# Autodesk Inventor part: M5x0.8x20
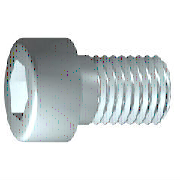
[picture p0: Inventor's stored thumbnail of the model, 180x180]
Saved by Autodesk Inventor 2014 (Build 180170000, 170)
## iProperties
IsCustomPart: 0
Created: 2015-11
Part Number: M5x0.8x20
Material: 스테인리스강
Description: 6각머리 태핑 나사
Document SubType Name: Modeling
Standard: KS B 1003
Designer: mdu
Standards Organization: KS
Language: ko-KR
Size Designation: M 5 x 20
Categories: <MemberInstance><Categories><Category DisplayName="조임쇠" InternalName="e4da775c-781d-43d5-af7c-5136215cf5a6" Mnemonic="FSTN"><Category DisplayName="볼트" InternalN
Density: 8.08 g/cm^3
Appearance: 반광택
Mass: 5.10181 g
Surface Area: 5.88237 cm^2
Volume: 0.631412 cm^3
Author: mdu
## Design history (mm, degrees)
sketch "스케치1"
  geometry: L1 (-1.167, 0)-(20, 0); L2 (20, 0)-(20, 2.5); L3 (20, 2.5)-(2, 2.5); L4 (2, 2.5)-(1.509, 2.5); L5 (1.509, 2.5)-(0, 2.5); L6 (0, 2.5)-(0, 4.25); L7 (0, 4.25)-(-5, 4.25); L8 (-5, 4.25)-(-5, 2.309); L9 (-5, 2.309)-(-2.5, 2.309); L10 (-2.5, 2.309)-(-1.167, 0); L11 (-10, 0)-(25, 0) reference; L12 (0, -0.85)-(0, 5.1) reference; L13 (2, 2.5)-(0, 2.5)
  constraints: 22 end point, 6 parallel, 2 collinear, 2 perpendicular, 1 horizontal, 1 point on line
  dimensions: "d1" = 18 distance from line of L3.end L2 (= GEL); "d2" = 0.49086 distance of L4.end L3.end (computed from GAL); "d3" = 5 distance between parallel lines of L8 L6 (= KOH); "d4" = 2.5 distance of L8.end L9.end (= INTI); "d5" = 60 deg angle of L10 L1; "d6" = 5 diameter of L3 L1 (= GD); "d7" = 5 diameter of L5 L1 (= BDM); "d8" = 4.6188 diameter of L9 L1 (= 1.1547 x SW); "d9" = 8.5 diameter of L7 L1 (= KOD); "d26" = 20 distance between parallel lines of L12 L2 (= NLG)
revolve "본체" sketch "스케치1" stored, may be unused: angle "d10" = 90 deg
sketch "스케치2"
  geometry: L1 (0, -5.95)-(0, 5.95) reference; L2 (-5.95, 0)-(5.95, 0) reference; L3 (2.309, 0)-(1.155, -2); L4 (1.155, -2)-(-1.155, -2); L5 (-1.155, -2)-(-2.309, 0); L6 (-2.309, 0)-(-1.155, 2); L7 (-1.155, 2)-(1.155, 2); L8 (1.155, 2)-(2.309, 0); 2 further points
  constraints: 12 end point, 1 coincident, 1 horizontal alignment, 1 point on line, 12 other
extrude "슬롯" join sketch "스케치2" stored distance "d11" = 10; taper "d12" = 0 deg
workplane "Work Plane1"
fillet "Fillet2" dims "d30" = 0.1 (= R)
body "Solid1"
fillet "모깎기1" dims "d17" = 0.5 (= RR)
feature "스레드" dims "d13" = 18 (= GEL), "d14" = 0
chamfer "모따기1" distance "d15" = 0.49076 (= -0.5 x SPD + 0.5 x GD); stored, may be unused: second distance "d16" = 0.49076 (= GUL), angle "d27" = 45 deg
other parameters: "GD" = 5 (= NND) [user parameter; used in 2 equation terms], "NLG" = 20 [user parameter; used in 1 equation term], "GEL" = 18 [user parameter; used in 2 equation terms], "KOD" = 8.5 [user parameter; used in 1 equation term], "KOH" = 5 [user parameter; used in 1 equation term], "INTI" = 2.5 [user parameter; used in 1 equation term], "GAL" = 0.49076 (= 0.61345 x PTC) [user parameter; used in 1 equation term], "GUL" = 0.49076 (= 0.61345 x PTC) [user parameter; used in 1 equation term], "BDM" = 5 (= NND) [user parameter; used in 1 equation term], "SW" = 4 [user parameter; used in 2 equation terms], "RR" = 0.5 [user parameter; used in 1 equation term], "SPD" = 4.01848 (= NND - 1.2269 x PTC) [user parameter; used in 1 equation term], "d19" = 0, "d28" = 0, "d29" = 0, "R" = 0.1 [user parameter; used in 1 equation term], "PHH" = 0.2 [user parameter], "GD1" = 4.01848 (= THREADDIA - 1.2269 x PTC) [user parameter], "THREADDIA" = 5 [user parameter; used in 1 equation term], "FAWI" = 45 deg [user parameter], "TPU" = 12.5 (computed from PTC) [user parameter], "PTC" = 0.8 [user parameter; used in 5 equation terms], "NND" = 5 [user parameter; used in 3 equation terms], "TOA" = 30 deg [user parameter], "E0" = 4.62 (= 1.155 x SW) [user parameter]
